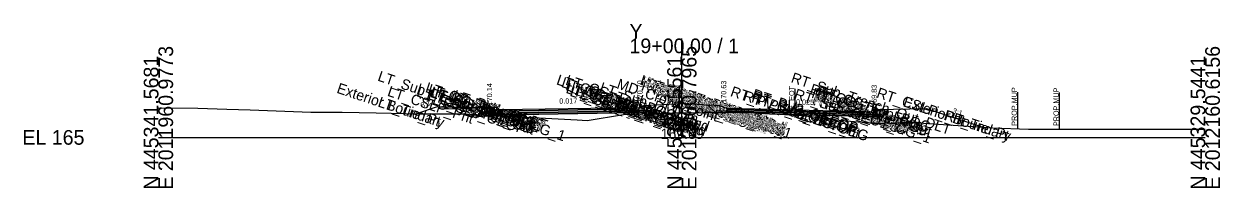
# Model space of a CAD drawing. Extents: x -26 to 3203, y -10 to 9532.
# Drawn here: x 974.3 to 1202.8, y 2990.3 to 3021.7 of the extents above; entities that cross this region are included whole.
import ezdxf

# ---------------------------------------------------------------- set-up
doc = ezdxf.new("R2010")
doc.units = 0
for name, color, linetype in [('Default', 7, 'Continuous'), ('Exist CMT Pavement', 7, 'Continuous'), ('Exist Cross Section Cell', 7, 'Continuous'), ('Exist XS Center Line Elevation Label', 7, 'Continuous'), ('Exist XS Ground Line', 7, 'Continuous'), ('Prop CMT Conc Surface', 7, 'Continuous'), ('Prop CMT Concrete Structures', 7, 'Continuous'), ('Prop CMT Pvmt Course 1', 7, 'Continuous'), ('Prop CMT Pvmt Course 1 CG', 7, 'Continuous'), ('Prop CMT Pvmt Course 2', 7, 'Continuous'), ('Prop CMT Pvmt Course 2 Wedge', 7, 'Continuous'), ('Prop CMT Pvmt Course 3', 7, 'Continuous'), ('Prop CMT Pvmt Course 3 Wedge', 7, 'Continuous'), ('Prop CMT Pvmt Surface', 7, 'Continuous'), ('Prop CMT Slope Grass', 7, 'Continuous'), ('Prop CMT Subgrade Earthwork', 7, 'Continuous'), ('Prop XS Hydro Elevations', 7, 'Continuous'), ('Prop XS Label Text', 7, 'Continuous'), ('Prop XS SE Text', 7, 'Continuous'), ('Prop XS Side Slope Text', 7, 'Continuous'), ('Scratch_Level_0', 7, 'Continuous')]:
    doc.layers.add(name, color=color, linetype=linetype)

msp = doc.modelspace()

# ---------------------------------------------------------------- linework, layer by layer
at = {"layer": 'Exist CMT Pavement'}
msp.add_lwpolyline([(1108.74, 3004.77), (1108.82, 3004.78), (1110.58, 3004.81), (1111.1, 3004.8), (1111.23, 3004.8), (1111.43, 3004.79), (1113.72, 3004.69), (1115.76, 3004.6), (1116.22, 3004.58), (1116.74, 3004.55), (1118.73, 3004.43), (1120.51, 3004.35), (1121.44, 3004.3), (1121.57, 3004.29), (1122.06, 3004.26), (1123.33, 3004.18), (1123.44, 3004.17), (1123.75, 3004.13)], dxfattribs=at)
at = {"layer": 'Exist Cross Section Cell'}
for p, q in [((1099.99, 3000.02), (1099.99, 3018.92)), ((999.99, 3000.02), (1099.99, 3000.02)), ((1099.99, 3000.02), (1199.99, 3000.02))]:
    msp.add_line(p, q, dxfattribs=at)
at = {"layer": 'Exist XS Ground Line'}
msp.add_lwpolyline([(999.99, 3005.69), (1007.53, 3005.58), (1013.04, 3005.42), (1017.55, 3005.3), (1029.11, 3004.84), (1032.03, 3004.85), (1035.08, 3004.81), (1041.57, 3004.73), (1044.48, 3004.62), (1049.99, 3004.5), (1057.62, 3004.55), (1058.26, 3004.53), (1080, 3003.35), (1081.9, 3003.27), (1088.87, 3004.41), (1098.14, 3004.69), (1099.11, 3004.7), (1099.47, 3004.71), (1099.99, 3004.71), (1100.65, 3004.71), (1101.22, 3004.72), (1101.62, 3004.72), (1103.99, 3004.76), (1106.23, 3004.77), (1108.14, 3004.77), (1108.82, 3004.78), (1110.58, 3004.81), (1111.43, 3004.79), (1113.72, 3004.69), (1115.76, 3004.6), (1116.22, 3004.58), (1116.74, 3004.55), (1118.73, 3004.43), (1120.51, 3004.35), (1121.57, 3004.29), (1122.06, 3004.26), (1123.44, 3004.17), (1123.75, 3004.13), (1129.35, 3003.39), (1137.34, 3002.69), (1143.39, 3002.93), (1159.39, 3001.82), (1166.24, 3001.6), (1187.14, 3001.58), (1196.96, 3001.59), (1197.89, 3001.59), (1198.93, 3001.58), (1199.99, 3001.58)], dxfattribs=at)
at = {"layer": 'Prop CMT Conc Surface'}
for points in [[(1058.74, 3005.74), (1053.74, 3005.84)], [(1063.24, 3005.15), (1063.24, 3005.65), (1062.74, 3005.65)], [(1065.24, 3005.27), (1063.24, 3005.15)], [(1091.24, 3005.7), (1091.99, 3005.71), (1091.99, 3005.88), (1092.75, 3006.13)], [(1108.74, 3005.63), (1107.99, 3005.65), (1107.99, 3005.81), (1107.23, 3006.06)], [(1136.74, 3004.85), (1136.74, 3005.35), (1137.24, 3005.35)], [(1134.74, 3004.98), (1136.74, 3004.85)]]:
    msp.add_lwpolyline(points, dxfattribs=at)
at = {"layer": 'Prop CMT Concrete Structures'}
for points in [[(1053.74, 3005.51), (1053.74, 3005.84)], [(1053.74, 3005.84), (1058.74, 3005.74)], [(1058.74, 3005.41), (1053.74, 3005.51)], [(1058.74, 3005.74), (1058.74, 3005.41)], [(1065.24, 3005.27), (1063.24, 3005.15), (1063.24, 3005.65), (1062.74, 3005.65)], [(1062.74, 3005.65), (1062.74, 3004.64), (1065.24, 3004.68)], [(1065.24, 3004.68), (1065.24, 3005.27)], [(1091.24, 3005.7), (1091.99, 3005.71), (1091.99, 3005.88), (1092.75, 3006.13)], [(1091.24, 3005.12), (1091.24, 3005.7)], [(1092.75, 3006.13), (1092.75, 3005.14)], [(1108.74, 3005.63), (1107.99, 3005.65), (1107.99, 3005.81), (1107.23, 3006.06)], [(1107.23, 3006.06), (1107.23, 3005.08)], [(1108.74, 3005.04), (1108.74, 3005.63)], [(1134.74, 3004.98), (1136.74, 3004.85), (1136.74, 3005.35), (1137.24, 3005.35)], [(1137.24, 3005.35), (1137.24, 3004.33), (1134.74, 3004.39)], [(1092.75, 3005.14), (1091.24, 3005.12)], [(1107.23, 3005.08), (1108.74, 3005.04)], [(1134.74, 3004.39), (1134.74, 3004.98)]]:
    msp.add_lwpolyline(points, dxfattribs=at)
at = {"layer": 'Prop CMT Pvmt Course 1'}
for points in [[(1091.24, 3005.7), (1065.24, 3005.27)], [(1065.24, 3005.02), (1091.24, 3005.45)], [(1065.24, 3005.27), (1065.24, 3005.02)], [(1091.24, 3005.45), (1091.24, 3005.7)], [(1091.24, 3005.45), (1091.24, 3005.45), (1091.24, 3005.45)], [(1108.74, 3005.63), (1134.74, 3004.98)], [(1108.74, 3005.38), (1108.74, 3005.63)], [(1134.74, 3004.73), (1123.75, 3005), (1108.74, 3005.38)], [(1108.74, 3005.38), (1108.74, 3005.38)], [(1134.74, 3004.98), (1134.74, 3004.73)]]:
    msp.add_lwpolyline(points, dxfattribs=at)
at = {"layer": 'Prop CMT Pvmt Course 1 CG'}
for points in [[(1065.24, 3004.68), (1062.24, 3004.63), (1061.9, 3004.29)], [(1061.9, 3004.29), (1065.24, 3004.35)], [(1065.24, 3004.35), (1065.24, 3004.68)], [(1091.24, 3005.12), (1093.25, 3005.15), (1093.57, 3004.82)], [(1091.24, 3004.78), (1091.24, 3005.12)], [(1093.57, 3004.82), (1091.24, 3004.78)], [(1108.74, 3005.04), (1106.73, 3005.09), (1106.4, 3004.77)], [(1106.4, 3004.77), (1108.74, 3004.71)], [(1108.74, 3004.71), (1108.74, 3005.04)], [(1134.74, 3004.39), (1137.74, 3004.32), (1138.08, 3003.98)], [(1134.74, 3004.06), (1134.74, 3004.39)], [(1138.08, 3003.98), (1134.74, 3004.06)]]:
    msp.add_lwpolyline(points, dxfattribs=at)
at = {"layer": 'Prop CMT Pvmt Course 2'}
for points in [[(1091.24, 3005.45), (1065.24, 3005.02)], [(1091.24, 3005.12), (1091.24, 3005.45)], [(1108.74, 3005.38), (1108.74, 3005.38)], [(1065.24, 3004.68), (1091.24, 3005.12)], [(1065.24, 3005.02), (1065.24, 3004.68)], [(1121.58, 3004.72), (1121.58, 3005.06)], [(1121.58, 3005.06), (1134.74, 3004.73)], [(1134.74, 3004.39), (1121.58, 3004.72)], [(1134.74, 3004.73), (1134.74, 3004.39)]]:
    msp.add_lwpolyline(points, dxfattribs=at)
msp.add_lwpolyline([(1108.74, 3005.38), (1108.74, 3005.04), (1108.74, 3005.04)], close=True, dxfattribs=at)
at = {"layer": 'Prop CMT Pvmt Course 2 Wedge'}
for points in [[(1108.74, 3005.04), (1108.74, 3005.38)], [(1108.74, 3005.38), (1108.82, 3005.38), (1110.58, 3005.33), (1111.1, 3005.32), (1111.23, 3005.31), (1111.43, 3005.31), (1113.72, 3005.25), (1115.76, 3005.2), (1116.22, 3005.19), (1116.74, 3005.18), (1118.73, 3005.13), (1120.51, 3005.08), (1121.58, 3005.06)], [(1121.58, 3004.72), (1120.51, 3004.75), (1118.73, 3004.79), (1116.74, 3004.84), (1116.22, 3004.86), (1115.76, 3004.87), (1113.72, 3004.92), (1111.43, 3004.98), (1111.23, 3004.98), (1111.1, 3004.99), (1110.58, 3005), (1108.82, 3005.04), (1108.74, 3005.04)], [(1121.58, 3005.06), (1121.58, 3004.72)]]:
    msp.add_lwpolyline(points, dxfattribs=at)
at = {"layer": 'Prop CMT Pvmt Course 3'}
for points in [[(1091.24, 3005.12), (1065.24, 3004.68)], [(1065.24, 3004.35), (1091.24, 3004.78)], [(1065.24, 3004.68), (1065.24, 3004.35)], [(1091.24, 3004.78), (1091.24, 3005.12)], [(1108.74, 3005.04), (1108.74, 3005.04), (1108.74, 3004.71), (1108.74, 3004.71)], [(1108.74, 3004.71), (1108.74, 3005.04)], [(1121.58, 3004.72), (1134.74, 3004.39)], [(1121.58, 3004.39), (1121.58, 3004.72)], [(1134.74, 3004.06), (1121.58, 3004.39)], [(1134.74, 3004.39), (1134.74, 3004.06)]]:
    msp.add_lwpolyline(points, dxfattribs=at)
at = {"layer": 'Prop CMT Pvmt Course 3 Wedge'}
for points in [[(1108.74, 3004.77), (1108.74, 3005.04)], [(1108.74, 3005.04), (1108.82, 3005.04), (1110.58, 3005), (1111.1, 3004.99), (1111.23, 3004.98), (1111.43, 3004.98), (1113.72, 3004.92), (1115.76, 3004.87), (1116.22, 3004.86), (1116.74, 3004.84), (1118.73, 3004.79), (1120.51, 3004.75), (1121.58, 3004.72)], [(1123.75, 3004.13), (1123.44, 3004.17), (1123.33, 3004.18), (1122.06, 3004.26), (1121.57, 3004.29), (1121.44, 3004.3), (1120.51, 3004.35), (1118.73, 3004.43), (1116.74, 3004.55), (1116.22, 3004.58), (1115.76, 3004.6), (1113.72, 3004.69), (1111.43, 3004.79), (1111.23, 3004.8), (1111.1, 3004.8), (1110.58, 3004.81), (1108.82, 3004.78), (1108.74, 3004.77)], [(1121.58, 3004.72), (1121.58, 3004.29)]]:
    msp.add_lwpolyline(points, dxfattribs=at)
at = {"layer": 'Prop CMT Pvmt Surface'}
for points in [[(1091.24, 3005.7), (1065.24, 3005.27)], [(1108.74, 3005.63), (1134.74, 3004.98)]]:
    msp.add_lwpolyline(points, dxfattribs=at)
at = {"layer": 'Prop CMT Slope Grass'}
msp.add_line((1107.23, 3006.06), (1099.68, 3006.51), dxfattribs=at)
for points in [[(1053.24, 3005.84), (1049.27, 3004.52)], [(1062.74, 3005.65), (1053.24, 3005.84)], [(1092.75, 3006.13), (1099.68, 3006.51)], [(1137.24, 3005.35), (1146.74, 3005.54)], [(1146.74, 3005.54), (1157.51, 3001.95)]]:
    msp.add_lwpolyline(points, dxfattribs=at)
at = {"layer": 'Prop CMT Subgrade Earthwork'}
for points in [[(1065.24, 3004.35), (1061.9, 3004.29), (1060.49, 3005.7)], [(1095, 3006.25), (1093.57, 3004.82)], [(1104.97, 3006.2), (1106.4, 3004.77)], [(1134.74, 3004.06), (1138.08, 3003.98), (1139.49, 3005.39)], [(1091.24, 3004.78), (1065.24, 3004.35)], [(1065.24, 3004.35), (1065.24, 3004.35)], [(1093.57, 3004.82), (1091.24, 3004.78)], [(1091.24, 3004.78), (1091.24, 3004.78)], [(1091.24, 3004.78), (1091.24, 3004.78)], [(1106.4, 3004.77), (1108.74, 3004.71)], [(1108.74, 3004.71), (1108.74, 3004.77)], [(1108.74, 3004.71), (1108.74, 3004.71)], [(1108.74, 3004.71), (1108.74, 3004.71)], [(1121.58, 3004.39), (1134.74, 3004.06)], [(1121.58, 3004.39), (1121.59, 3004.29)], [(1134.74, 3004.06), (1134.74, 3004.06)]]:
    msp.add_lwpolyline(points, dxfattribs=at)
at = {"layer": 'Prop XS Label Text'}
for p, q in [((1099.48, 3009.69), (1099.48, 3004.69)), ((1121.58, 3009.29), (1121.58, 3004.29)), ((1164.1, 3008.65), (1164.1, 3001.65)), ((1172.1, 3008.61), (1172.1, 3001.61))]:
    msp.add_line(p, q, dxfattribs=at)

# ---------------------------------------------------------------- texts
at = {"layer": 'Default'}
msp.add_text('-', height=0.0001, dxfattribs=at).set_placement((999.99, 3000.02))
at = {"layer": 'Exist Cross Section Cell'}
for s, p in [('Y', (1089.99, 3018.92)), ('19+00.00 / 1', (1089.99, 3016.12)), ('EL 165', (973.99, 2998.62))]:
    msp.add_text(s, height=2.8, dxfattribs=at).set_placement(p)
for s, p in [('E 2011960.9773', (1002.79, 2990.02)), ('E 2012060.7965', (1102.79, 2990.02)), ('E 2012160.6156', (1202.79, 2990.02)), ('N 445341.5681', (999.99, 2990.02)), ('N 445335.5561', (1099.99, 2990.02)), ('N 445329.5441', (1199.99, 2990.02))]:
    msp.add_text(s, height=2.8, rotation=90, dxfattribs=at).set_placement(p)
at = {"layer": 'Exist XS Center Line Elevation Label'}
msp.add_text('169.69', height=2, dxfattribs=at).set_placement((1095.96, 2999.71))
at = {"layer": 'Prop XS Hydro Elevations'}
for s, p in [('170.14', (1063.74, 3006.15)), ('170.70', (1092.49, 3006.71)), ('170.63', (1108.49, 3006.65)), ('169.83', (1137.24, 3005.85))]:
    msp.add_text(s, height=1, rotation=90, dxfattribs=at).set_placement(p)
at = {"layer": 'Prop XS Label Text'}
for s, p in [('E. EOT', (1099.38, 3005.72)), ('E. EOT', (1121.48, 3005.32)), ('PROP.MUP', (1164, 3002.23)), ('PROP.MUP', (1172, 3002.18))]:
    msp.add_text(s, height=1, rotation=90, dxfattribs=at).set_placement(p)
at = {"layer": 'Prop XS SE Text'}
for s, rotation, p in [('0.017', 0.9555, (1076.58, 3006.46)), ('0.025', 358.5679, (1121.79, 3006.3))]:
    msp.add_text(s, height=1, rotation=rotation, dxfattribs=at).set_placement(p)
at = {"layer": 'Prop XS Side Slope Text'}
for rotation, p in [(18.4349, (1050.28, 3005.63)), (341.5651, (1151.61, 3004.7))]:
    msp.add_text('3:1', height=1, rotation=rotation, dxfattribs=at).set_placement(p)
at = {"layer": 'Scratch_Level_0'}
for s, p in [('LT_Sub_Trench_Out_DLT', (1041.74, 3010.89)), ('RT_Sub_Trench_Out_DLT', (1120.7, 3010.6)), ('Exterior Boundary', (1033.91, 3008.59)), ('LT_CSLP_Pnt', (1043.6, 3008)), ('LT_CG_Top_Face', (1050.83, 3008.73)), ('LT_CG_Top_BOC', (1051.3, 3008.41)), ('LT_CG_Top_Face_Med', (1075.89, 3010.19)), ('LT_CG_Top_Gut_Med', (1076.82, 3009.71)), ('LT_CG_Top_BOC_Med', (1077.62, 3010.12)), ('LT_CG_Bot_BOC_Med', (1077.65, 3009.12)), ('LT_CG_Bot_IE_Med', (1077.7, 3008.58)), ('LT_Sub_IEOT_CG_1', (1078.46, 3007.99)), ('LT_Sub_DLT_In', (1084.12, 3008.72)), ('MD_Crown Point', (1087.4, 3009.41)), ('RT_CG_Top_Face_Med', (1091.85, 3010.14)), ('RT_CG_Top_BOC_Med', (1092.06, 3010.06)), ('RT_CG_Bot_BOC_Med', (1092.09, 3009.07)), ('RT_CG_Top_Gut_Med', (1092.77, 3009.66)), ('RT_Sub_DLT_In', (1094.19, 3008.69)), ('RT_CG_Bot_IE_Med', (1095.15, 3008.52)), ('RT_PV_Sub_Tie_In', (1095.62, 3008.09)), ('RT_PV_Sub_Tie_Out', (1109.12, 3007.96)), ('RT_CG_Top_Face', (1124.29, 3008.44)), ('RT_CG_Top_BOC', (1125.76, 3008.12)), ('LT_Tie_Pt', (1041.78, 3005.96)), ('LT_CG1_Shelf_Out', (1049.16, 3007.94)), ('LT_CG_Bot_BOC', (1051.33, 3007.39)), ('LT_CG_Top_Gut', (1051.76, 3007.92)), ('LT_Sub_OEOT_CG_1', (1051.85, 3007.76)), ('LT_Sub_OEOP', (1052.2, 3006.47)), ('LT_CG_Bot_IE', (1055.35, 3006.92)), ('LT_Sub_OEOT', (1055.51, 3006.54)), ('LT_PV2_OEOT', (1055.6, 3007.18)), ('LT_PV3_OEOT', (1055.6, 3006.84)), ('LT_PV1_OEOT', (1056.14, 3007.25)), ('LT_Sub_OEEOP', (1080.69, 3007.25)), ('LT_PV2_OEEOP', (1080.78, 3007.88)), ('LT_PV3_OEEOP', (1080.78, 3007.55)), ('LT_Sub_IEEOP', (1081.3, 3007.04)), ('LT_PV2_IEEOP', (1081.39, 3007.68)), ('LT_CG1_Shelf_In', (1081.71, 3007.94)), ('LT_Sub_PGL', (1082.49, 3006.64)), ('LT_PV2_PGL', (1082.58, 3007.28)), ('LT_PV1_PGL', (1083.12, 3007.35)), ('LT_Sub_IEOP', (1084.49, 3006.8)), ('RT_CG1_Shelf_In', (1095.15, 3007.9)), ('RT_Sub_IEOT_CG_1', (1095.92, 3007.93)), ('RT_PV_IEEOP_EG', (1097.17, 3007.58)), ('RT_Sub_IEOP', (1097.27, 3006.76)), ('RT_Sub_IEEOP', (1098.75, 3006.98)), ('RT_PV2_IEEOP', (1098.84, 3007.62)), ('RT_PV3_IEEOP', (1098.84, 3007.29)), ('RT_Sub_PGL', (1099.95, 3006.59)), ('RT_PV2_PGL', (1100.04, 3007.22)), ('RT_PV3_PGL', (1100.04, 3006.89)), ('RT_PV1_PGL', (1100.58, 3007.29)), ('RT_PV_OEEOP_EG', (1111.57, 3007.14)), ('RT_Sub_OEEOP', (1113.16, 3006.81)), ('RT_PV2_OEEOP', (1113.25, 3007.45)), ('RT_PV3_OEEOP', (1113.25, 3007.12)), ('RT_Sub_OEOT_CG_1', (1121.3, 3007.48)), ('RT_CG1_Shelf_Out', (1124.62, 3007.64)), ('RT_CG_Bot_IE', (1124.81, 3006.65)), ('RT_Sub_OEOT', (1124.96, 3006.26)), ('RT_PV2_OEOT', (1125.05, 3006.9)), ('RT_PV3_OEOT', (1125.05, 3006.57)), ('RT_CG_Top_Gut', (1125.21, 3007.63)), ('RT_PV1_OEOT', (1125.59, 3006.97)), ('RT_CG_Bot_BOC', (1125.79, 3007.09)), ('RT_Sub_OEOP', (1128.33, 3006.17)), ('RT_CSLP_Pnt', (1137.05, 3007.71)), ('Exterior Boundary', (1142.15, 3006.01)), ('RT_Tie_Pt', (1149.98, 3003.4))]:
    msp.add_text(s, height=2, rotation=341.5651, dxfattribs=at).set_placement(p)

doc.saveas('drawing.dxf')
